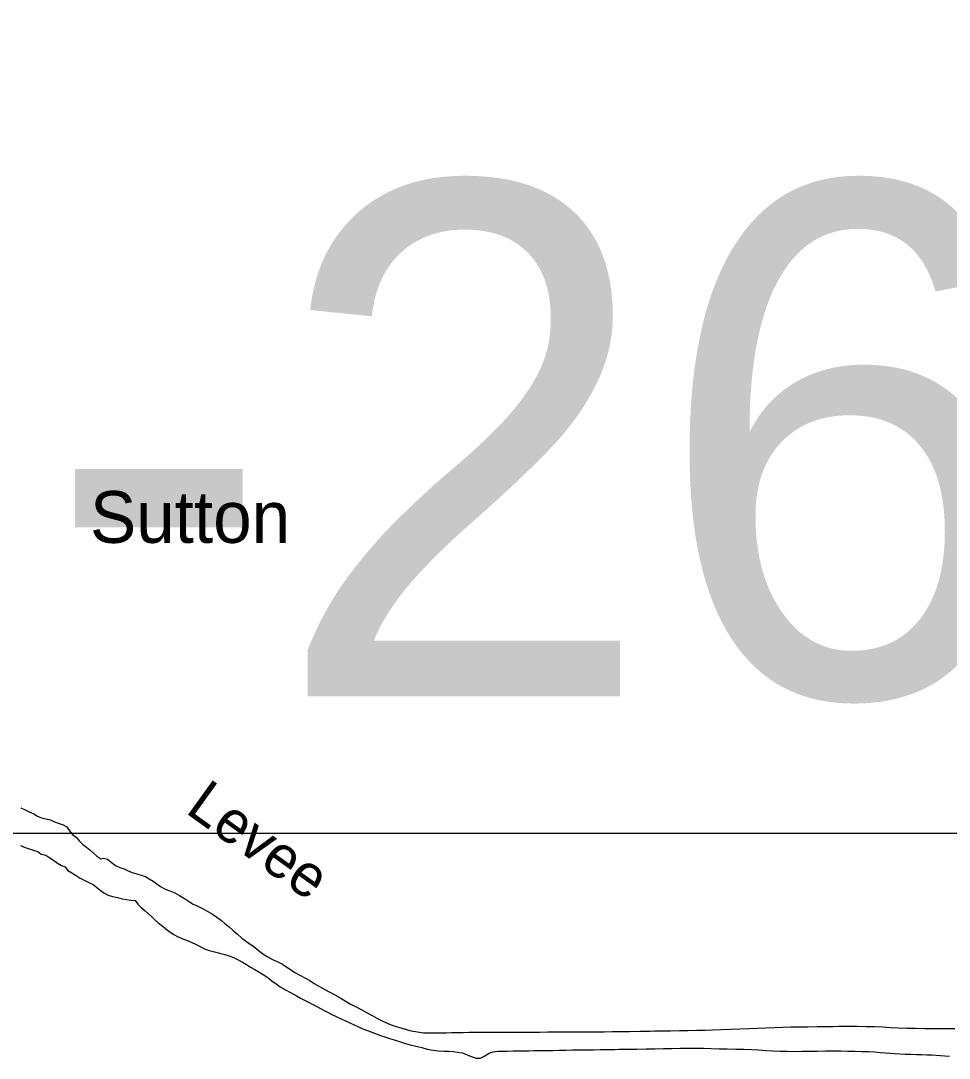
# Model space of a CAD drawing. Extents: x 1945482 to 2853149, y 66427 to 1015778.
# Drawn here: x 2300512 to 2303748, y 198502 to 202121 of the extents above; entities that cross this region are included whole.
import ezdxf

# ---------------------------------------------------------------- set-up
doc = ezdxf.new("R2010")
doc.units = 0
for name, color, linetype in [('Old_Level_21', 7, 'Continuous'), ('Old_Level_3', 7, 'Continuous'), ('Old_Level_60', 7, 'Continuous')]:
    doc.layers.add(name, color=color, linetype=linetype)

msp = doc.modelspace()

# ---------------------------------------------------------------- linework, layer by layer
at = {"layer": 'Old_Level_3'}
msp.add_lwpolyline([(2304961.1, 199286.1), (2298124.6, 199286.1), (2298124.6, 202204.8), (2304961.1, 202204.8), (2304961.1, 199286.1)], dxfattribs=at)
at = {"layer": 'Old_Level_60'}
for points in [[(2300511.5, 199375.6), (2300527.2, 199368.6), (2300541.5, 199361.6), (2300556.7, 199354.2), (2300570, 199346.8), (2300584.2, 199340.4), (2300599.5, 199337.6), (2300615.7, 199333.2), (2300629.5, 199326.8), (2300645, 199320.4), (2300659.5, 199315.8), (2300672.7, 199309), (2300681.7, 199295.4), (2300692.5, 199282), (2300705.5, 199272.4), (2300715.5, 199260.4), (2300727.5, 199248), (2300740.5, 199238.4), (2300752.2, 199228.6), (2300764.5, 199218), (2300776.7, 199207.2), (2300790.5, 199197), (2300799.7, 199200), (2300813.5, 199196.8), (2300826.2, 199185.6), (2300841.5, 199174.6), (2300857.5, 199166.8), (2300872.2, 199163), (2300885.7, 199156.2), (2300900.5, 199149.6), (2300915.7, 199145), (2300931.2, 199140.8), (2300946.5, 199135.6), (2300959.7, 199127.8), (2300973, 199119.4), (2300985.5, 199110.6), (2300998.7, 199100.8), (2301015.5, 199092.2), (2301031.5, 199086.4), (2301048.5, 199079.4), (2301065.2, 199070), (2301082.2, 199058.8), (2301099.5, 199047.4), (2301113, 199039.8), (2301128.7, 199032.4), (2301147, 199023), (2301163.5, 199014), (2301179.5, 199005), (2301194.7, 198994.6), (2301211, 198982.2), (2301223.5, 198972.4), (2301238.2, 198960), (2301251.5, 198948), (2301267.2, 198934.2), (2301282.7, 198920.8), (2301294.7, 198912), (2301307.2, 198903.4), (2301325.5, 198890.4), (2301339.5, 198878.8), (2301355.5, 198865.8)], [(2300510.5, 199244.2), (2300526.7, 199237.2)], [(2300526.7, 199237.2), (2300541.5, 199232.4), (2300556.2, 199227.2), (2300571, 199222.8), (2300583.2, 199213.6), (2300598.5, 199210.4), (2300613.2, 199201.4), (2300625.7, 199193), (2300640, 199182.2), (2300653.5, 199174), (2300666.2, 199169.2), (2300675.7, 199156.8), (2300689.5, 199149), (2300704.5, 199139.2), (2300718.7, 199130.4), (2300733.2, 199122.6), (2300749.5, 199115.2), (2300763.5, 199108.2), (2300775.7, 199099), (2300788.5, 199088.6), (2300801.7, 199079), (2300816.2, 199071.2), (2300831.5, 199066), (2300848.7, 199062.6), (2300865.2, 199058.4), (2300880.2, 199055.2), (2300895.7, 199053), (2300910.5, 199052), (2300919.5, 199039.6), (2300931.2, 199027.8), (2300945.2, 199015.8), (2300957.5, 199006), (2300968.7, 198995.6), (2300979.5, 198984.8), (2300990.7, 198974.6), (2301003.5, 198964.6), (2301015.7, 198954.4), (2301029, 198944.2), (2301045, 198933.6), (2301058.2, 198926.4), (2301072.7, 198919.8), (2301089.7, 198913.6), (2301106.2, 198907), (2301123, 198898.4), (2301136.5, 198891.6), (2301152.7, 198884), (2301168.5, 198878), (2301187, 198872.8), (2301204, 198868.6), (2301222.5, 198863.6), (2301238.7, 198858.8), (2301255.7, 198852.6), (2301270, 198845.8), (2301285, 198837), (2301298.2, 198828.8), (2301313, 198819.4), (2301327.5, 198811), (2301344.5, 198801.4), (2301358.7, 198792.4), (2301373.5, 198782), (2301386.5, 198772.2), (2301401.5, 198761.2), (2301416, 198751.6), (2301434.2, 198740.8), (2301452.2, 198730.8), (2301472.7, 198719.4), (2301486.5, 198712), (2301500.5, 198704.6), (2301514.2, 198697.8), (2301527.7, 198691), (2301546.5, 198681.4), (2301567.5, 198670.2), (2301581.2, 198662.6), (2301596, 198655), (2301611.5, 198647.4), (2301628.2, 198640), (2301644, 198632.8), (2301658.7, 198625.4), (2301673.5, 198618.2), (2301688.5, 198611.4), (2301704.5, 198604.8), (2301720, 198598.6), (2301735, 198592.6), (2301750.2, 198587), (2301765.5, 198581.6), (2301781.2, 198576.4), (2301797.5, 198571.4), (2301813.2, 198566.4), (2301828.2, 198561.6), (2301848.5, 198554.8), (2301869.5, 198548.4), (2301889, 198544), (2301909.7, 198539), (2301928, 198534.2), (2301949, 198530.2), (2301968, 198528.2), (2301987.5, 198527.2), (2302003.5, 198526.4), (2302019.2, 198525.4)], [(2301355.5, 198865.8), (2301370.5, 198856.4), (2301388.7, 198846.8), (2301405.2, 198839), (2301421.7, 198830.8), (2301436, 198822.2), (2301451.5, 198811.2), (2301466.5, 198801.4), (2301484.5, 198791.2), (2301501.5, 198782.4), (2301519.5, 198772.6), (2301535, 198763.2), (2301552.5, 198752.6), (2301569.2, 198742.8), (2301588.5, 198732.4), (2301606.2, 198723), (2301625.5, 198712.4), (2301642.5, 198702), (2301660.7, 198691.2), (2301678.2, 198682), (2301698.7, 198671.8), (2301717.2, 198662), (2301736.2, 198651.2), (2301752.7, 198641.8), (2301771, 198632.4), (2301788.5, 198624.6), (2301809, 198616.6), (2301829, 198610), (2301851.5, 198603.4), (2301872.2, 198598.2), (2301894.5, 198593.6), (2301915, 198590.8), (2301937.2, 198590.2), (2301957.5, 198590.6), (2301979.7, 198590.8), (2301995.5, 198591.2), (2302013.5, 198591.4), (2302032.7, 198591.8), (2302053.5, 198592), (2302073.7, 198592.4), (2302093.5, 198592.6), (2302113.5, 198592.8), (2302133.2, 198592.8), (2302152.7, 198592.6), (2302171.7, 198592.6), (2302191.2, 198592.8), (2302210.7, 198592.8), (2302230.5, 198592.8), (2302251.5, 198592.6), (2302273.2, 198592.6), (2302296.2, 198592.8), (2302321.5, 198593.4), (2302349.5, 198593.6), (2302379, 198594.2), (2302408.5, 198594.4), (2302437.2, 198594.2), (2302465, 198594)], [(2302465, 198594), (2302492, 198593.8), (2302519, 198594), (2302545.7, 198594.4), (2302573.7, 198595), (2302602.5, 198595.4), (2302634.2, 198595.8), (2302669.2, 198596.4), (2302685, 198596.6), (2302706.2, 198597), (2302722, 198597.2), (2302742.5, 198597.4), (2302776.2, 198598), (2302808.2, 198598.6), (2302838.7, 198599), (2302868.2, 198599.4), (2302896.2, 198600.4), (2302923.5, 198601.6), (2302953, 198602.8), (2302984.7, 198604), (2303018.5, 198605), (2303051.5, 198606), (2303081.2, 198606.6), (2303109.5, 198607.6), (2303139.2, 198609), (2303168.5, 198610.2), (2303196.5, 198611), (2303224.7, 198611.4), (2303254.5, 198612), (2303289, 198612.4), (2303304.5, 198612.8), (2303326.5, 198613), (2303342.2, 198613.2), (2303363.2, 198613.4), (2303396.7, 198613.8), (2303427.7, 198613.8), (2303458.5, 198613.2), (2303487.7, 198612.2), (2303515.7, 198611.2), (2303543, 198609.8), (2303570.2, 198608.6), (2303600, 198607.2), (2303630.7, 198606.6), (2303662, 198606.2), (2303691.7, 198606.2), (2303718.5, 198606.2), (2303742.7, 198605.8), (2303767.5, 198605.6)], [(2302019.2, 198525.4), (2302034.5, 198523.4), (2302051, 198521.2), (2302067.5, 198513.8), (2302082.2, 198507.6), (2302098.7, 198502), (2302114.7, 198502.2), (2302129.5, 198510), (2302144, 198519.2), (2302158.7, 198524.6), (2302174.7, 198526.6), (2302190.5, 198527), (2302207.7, 198527.2), (2302228.5, 198527.6), (2302249.7, 198527.8), (2302265.5, 198528.2), (2302282.5, 198528.4), (2302301.5, 198528.6), (2302322, 198529), (2302344, 198529.4), (2302366.5, 198529.6), (2302389, 198530), (2302411.5, 198530.4), (2302435, 198530.8), (2302459.5, 198531.2), (2302483.7, 198531.4), (2302507.7, 198531.8), (2302531.7, 198532.2), (2302556.5, 198532.6), (2302582.2, 198533), (2302597.7, 198533.2), (2302627.5, 198533.8), (2302659.2, 198534.2), (2302691.5, 198534.8), (2302722.2, 198535.2), (2302752, 198535.6), (2302781.7, 198536.2), (2302811.2, 198536.6), (2302839.7, 198537), (2302866.7, 198537.2), (2302892.5, 198536.8), (2302918.7, 198536.2), (2302946, 198535.4), (2302974.5, 198535), (2303004.2, 198534.2), (2303032.5, 198533.4), (2303058.7, 198532.2), (2303083.5, 198530.8), (2303108.5, 198529.4), (2303133.5, 198528.2), (2303158.5, 198527.2), (2303183.5, 198526.4), (2303208.2, 198526), (2303234.2, 198526.4), (2303260.7, 198526.8), (2303288.2, 198527.2)], [(2303288.2, 198527.2), (2303316.5, 198527.6), (2303344.2, 198527.6), (2303370, 198527.6), (2303394.7, 198527.2), (2303419, 198526.8), (2303443.2, 198526), (2303467.2, 198525.2), (2303488.7, 198524), (2303507.5, 198522.4), (2303524.5, 198520.8), (2303541.2, 198519.4), (2303558, 198518), (2303576, 198517), (2303594.7, 198516.2), (2303614.7, 198515.8), (2303634.2, 198515.2), (2303652.7, 198514.8), (2303670.5, 198514), (2303687.2, 198513.4), (2303702.5, 198512.6), (2303718, 198511.8), (2303733.5, 198510.8), (2303749.2, 198509.4)]]:
    msp.add_lwpolyline(points, dxfattribs=at)

# ---------------------------------------------------------------- texts
at = {"layer": 'Old_Level_21'}
msp.add_text('Sutton', height=180.45, dxfattribs=at).set_placement((2300753.1, 200299.6))
msp.add_text('Levee', height=147.64, rotation=324.3188, dxfattribs=at).set_placement((2301081.5, 199360.7))
at = {"layer": 'Old_Level_3'}
msp.add_text('R-2633', height=1788.88, dxfattribs=at).set_placement((2298866.9, 199764.4))

doc.saveas('drawing.dxf')
